(* Logix 5000 project; controller TEG17328 vendor 1 type 14 code 54 rev 16.23; software revision 16.04 *)

TASK MainTask (continuous, watchdog 500 ms) : MainProgram

MODULES
   Local : vendor 1 type 14 code 54 (ICP 2, rev 16.23)
      MNETC : vendor 1 type 0 code 15 (ICP 1, rev 1.1, Output RPI 5 ms)
END_MODULES

TYPE MNETCBLOCKSTATS :   // This object is used to store the block transfer statistics for the MVI56E-MNETC module.
STRUCT
   Read : INT;   // Total number of read block transfers
   Write : INT;   // Total number of write block transfers
   Parse : INT;   // Total number of blocks parsed
   Event : INT;   // Total number of event blocks received
   Cmd : INT;   // Total number of command blocks received
   Err : INT;   // Total number of block transfer errors
END_STRUCT
END_TYPE

TYPE MNETCCLIENTSTATS :   // This object is used to store the port statistics for an MVI56E-MNETC port.
STRUCT
   CmdReq : INT;   // Total number of command list requests sent
   CmdResp : INT;   // Total number of command list responses received
   CmdErr : INT;   // Total number of command list errors
   Requests : INT;   // Total number of requests for port
   Responses : INT;   // Total number of responses for port
   ErrSent : INT;   // Total number of errors sent
   ErrRec : INT;   // Total number of errors received
   CfgErrWord : INT;   // Configuration Error Word
   CurErr : INT;   // Current Error code
   LastErr : INT;   // Last recorded error code
END_STRUCT
END_TYPE

TYPE MNETCCLOCKTYPE :   // Allows read/write of clock value between the module and processor
STRUCT
   Read : BOOL;   // Reads current time from the module
   Write : BOOL;   // Writes current time from the module
   Config : MNETCDATETIME;   // Date and time configuration read or written between the module and processor
END_STRUCT
END_TYPE

TYPE MNETCCMDCLIENTSEQ_PENDING :   // Event sequence event cmd pending status
STRUCT
   Trigger : BOOL;   // Triggers event sequence cmd pending status
   Client0_QueueCount : SINT;   // Command queue count for client 0
   Client0_WaitingMsgs : SINT;   // Event sequence messages waiting for client 0
   Client1_QueueCount : SINT;   // Command queue count for client 1
   Client1_WaitingMsgs : SINT;   // Event sequence messages waiting for client 1
   Client2_QueueCount : SINT;   // Command queue count for client 2
   Client2_WaitingMsgs : SINT;   // Event sequence messages waiting for client 2
   Client3_QueueCount : SINT;   // Command queue count for client 3
   Client3_WaitingMsgs : SINT;   // Event sequence messages waiting for client 3
   Client4_QueueCount : SINT;   // Command queue count for client 4
   Client4_WaitingMsgs : SINT;   // Event sequence messages waiting for client 4
   Client5_QueueCount : SINT;   // Command queue count for client 5
   Client5_WaitingMsgs : SINT;   // Event sequence messages waiting for client 5
   Client6_QueueCount : SINT;   // Command queue count for client 6
   Client6_WaitingMsgs : SINT;   // Event sequence messages waiting for client 6
   Client7_QueueCount : SINT;   // Command queue count for client 7
   Client7_WaitingMsgs : SINT;   // Event sequence messages waiting for client 7
   Client8_QueueCount : SINT;   // Command queue count for client 8
   Client8_WaitingMsgs : SINT;   // Event sequence messages waiting for client 8
   Client9_QueueCount : SINT;   // Command queue count for client 9
   Client9_WaitingMsgs : SINT;   // Event sequence messages waiting for client 9
   Client10_QueueCount : SINT;   // Command queue count for client 10
   Client10_WaitingMsgs : SINT;   // Event sequence messages waiting for client 10
   Client11_QueueCount : SINT;   // Command queue count for client 11
   Client11_WaitingMsgs : SINT;   // Event sequence messages waiting for client 11
   Client12_QueueCount : SINT;   // Command queue count for client 12
   Client12_WaitingMsgs : SINT;   // Event sequence messages waiting for client 12
   Client13_QueueCount : SINT;   // Command queue count for client 13
   Client13_WaitingMsgs : SINT;   // Event sequence messages waiting for client 13
   Client14_QueueCount : SINT;   // Command queue count for client 14
   Client14_WaitingMsgs : SINT;   // Event sequence messages waiting for client 14
   Client15_QueueCount : SINT;   // Command queue count for client 15
   Client15_WaitingMsgs : SINT;   // Event sequence messages waiting for client 15
   Client16_QueueCount : SINT;   // Command queue count for client 16
   Client16_WaitingMsgs : SINT;   // Event sequence messages waiting for client 16
   Client17_QueueCount : SINT;   // Command queue count for client 17
   Client17_WaitingMsgs : SINT;   // Event sequence messages waiting for client 17
   Client18_QueueCount : SINT;   // Command queue count for client 18
   Client18_WaitingMsgs : SINT;   // Event sequence messages waiting for client 18
   Client19_QueueCount : SINT;   // Command queue count for client 19
   Client19_WaitingMsgs : SINT;   // Event sequence messages waiting for client 19
   Client20_QueueCount : SINT;   // Command queue count for client 20
   Client20_WaitingMsgs : SINT;   // Event sequence messages waiting for client 20
   Client21_QueueCount : SINT;   // Command count for client 21
   Client21_WaitingMsgs : SINT;   // Event sequence messages waiting for client 21
   Client22_QueueCount : SINT;   // Command queue count for client 22
   Client22_WaitingMsgs : SINT;   // Event sequence messages waiting for client 22
   Client23_QueueCount : SINT;   // Command queue count for client 23
   Client23_WaitingMsgs : SINT;   // Event sequence messages waiting for client 23
   Client24_QueueCount : SINT;   // Command queue count for client 24
   Client24_WaitingMsgs : SINT;   // Event sequence messages waiting for client 24
   Client25_QueueCount : SINT;   // Command queue count for client 25
   Client25_WaitingMsgs : SINT;   // Event sequence messages waiting for client 25
   Client26_QueueCount : SINT;   // Command queue count for client 26
   Client26_WaitingMsgs : SINT;   // Event sequence messages waiting for client 26
   Client27_QueueCount : SINT;   // Command queue count for client 27
   Client27_WaitingMsgs : SINT;   // Event sequence messages waiting for client 27
   Client28_QueueCount : SINT;   // Command queue count for client 28
   Client28_WaitingMsgs : SINT;   // Event sequence message waiting for client 28
   Client29_QueueCount : SINT;   // Command queue count for client 29
   Client29_WaitingMsgs : SINT;   // Event sequence messages waiting for client 29
END_STRUCT
END_TYPE

TYPE MNETCCMDCONTROL :   // MVI56E-MNETC Command Control
STRUCT
   ClientID : INT;   // Block5000 Client Identification by Index number 0 to 29
   CMDqty : INT;   // Block5000 command quantity
   CmdIndex : INT[16];   // Contains index in the command list for the 1st command to be entered into Command queue
   WriteCmdBits : INT[30];   // Command Bit control ClientID(0 to 29)
END_STRUCT
END_TYPE

TYPE MNETCCONTROL :   // Values used by program for data transfer operation between the module and the processor.
STRUCT
   BootTimer : TIMER;   // Timer used to clear both cold and warm boot requests
   ColdBoot : BOOL;   // Hardware reset of the Module
   WarmBoot : BOOL;   // Configuration data reset in the Module.
   ResetStatus : BOOL;   // Resets module status
   CmdID : INT;   // Command ID from 1 to 16
   CmdControl : MNETCCMDCONTROL;   // Holds Command Control statistics
   CmdControlPending : BOOL;   // Halts rung until Module is ready.
   CmdControlTrigger : BOOL;   // Command Control Trigger
   IPAddress : MNETCIPADDRESS;   // Getting and Setting IP address to and from Module
   EventCmd : MNETCEVENTCMD;   // Holds Event Command configuration
   EventSeqCmd : MNETCEVENTCMD_SEQ;   // Event Sequence Commands
END_STRUCT
END_TYPE

TYPE MNETCDATA :   // Contains Read Data (data read from the module to the processor) and Write Data (data written from the processor to the module)
STRUCT
   ReadData : INT[600];   // Data read from module. Set array equal to the size set in the Configuration file.
   WriteData : INT[600];   // Data to write to module. Set array equal to the size set in the Configuration file.
END_STRUCT
END_TYPE

TYPE MNETCDATETIME :   // Stores the date and time value
STRUCT
   Year : DINT;   // Displays module current year
   Month : DINT;   // Displays Module current month
   Day : DINT;   // Displays Module current day
   Hour : DINT;   // Displays Module current hour
   Minute : DINT;   // Displays Module current minute
   Seconds : DINT;   // Displays Module current second
END_STRUCT
END_TYPE

TYPE MNETCETHERNET :   // Stores the MVI56E-MNETC IP settings
STRUCT
   IP : INT[4];   // Module IP address
   Netmask : INT[4];   // Net mask used by the Module
   Gateway : INT[4];   // Gateway used by the module
END_STRUCT
END_TYPE

TYPE MNETCETHERNETTYPE :   // Allows read/write Ethernet settings between the module and processor
STRUCT
   Read : BOOL;   // Enable Ethernet configuration transfer from module to processor
   Write : BOOL;   // Enable Ethernet configuration transfer from processor to module
   Config : MNETCETHERNET;   // Module ethernet configurations ip, netmask and gateway
END_STRUCT
END_TYPE

TYPE MNETCEVENTCMD :   // Event command data structure
STRUCT
   Trigger : BOOL;   // Triggers event command
   ClientID : INT;   // Client ID for event command
   Cmd : MNETCEVENTCMD_SINGLE[30];   // Event command list
END_STRUCT
END_TYPE

TYPE MNETCEVENTCMD_SEQ :   // Data structure to use for each event command with status tracking by sequence number (blocks 4000 to 4029).
STRUCT
   Trigger : BOOL;   // Trigger Event Sequence Command
   ClientID : INT;   // Client ID for event sequence command (0-29)
   IP0 : INT;   // First digit of IP address
   IP1 : INT;   // Second digit of IP address
   IP2 : INT;   // Third digit of IP address
   IP3 : INT;   // Last digit of IP address
   ServPort : INT;   // TCP Service Port number (0-65535), 502 for MBAP, 2000 for MNET
   Node : INT;   // Modbus slave node address (0 to 247)
   DBAddress : INT;   // Module internal database to use with message
   Count : INT;   // Register or data point count
   Swap : INT;   // Swap code to use with functions 3 and 4
   Function : INT;   // Modbus function code for message
   Address : INT;   // Address to interface within device
   Sequence : INT;   // Unique sequence number to keep track of status code
END_STRUCT
END_TYPE

TYPE MNETCEVENTCMD_SEQSTAT :   // Event Command Sequence Status for one client
STRUCT
   Trigger : BOOL;   // Triggers event sequence command
   ClientID : INT;   // Selects ClientID
   Client : MNETCEVENTCMD_SEQSTAT_CLIENT[30];   // Error Status Event
END_STRUCT
END_TYPE

TYPE MNETCEVENTCMD_SEQSTAT_CLIENT :   // Event Command Sequence Status for one client
STRUCT
   Count : INT;   // Number of event commands received
   Cmd : MNETCEVENTCMD_SEQSTAT_SEQ_ERR[15];   // Error Status Event
END_STRUCT
END_TYPE

TYPE MNETCEVENTCMD_SEQSTAT_SEQ_ERR :   // Mnet event status of sequence event commands
STRUCT
   Sequence : INT;   // Sequence Number
   Error : INT;   // Error Code
END_STRUCT
END_TYPE

TYPE MNETCEVENTCMD_SINGLE :   // Data structure to use for Event message generation.
STRUCT
   IP0 : INT;   // First digit of IP address
   IP1 : INT;   // Second digit of IP address
   IP2 : INT;   // Third digit of IP address
   IP3 : INT;   // Last digit of IP address
   ServPort : INT;   // TCP Service Port number (0-65535), 502 for MBAP, 2000 for MNET
   Node : INT;   // Modbus slave node address (0 to 247)
   DBAddress : INT;   // Module internal database to use with message
   Count : INT;   // Register or data point count
   Swap : INT;   // Swap code to use with functions 3 and 4
   Function : INT;   // Modbus function code for message
   Address : INT;   // Address to interface with in device
END_STRUCT
END_TYPE

TYPE MNETCINITOUTDATA :   // Used to bring the Module into a known state after a restart operation.
STRUCT
   InitOutBlkIDLim : INT;   // Block Index Limit for ReadData size of the array
END_STRUCT
END_TYPE

TYPE MNETCIPADDRESS :   // Data structure to get and set the IP address of the module.
STRUCT
   IPGetTrigger : BOOL;   // Gets IP address.
   IPReceived : INT[4];   // IP address received.
   IPSetTrigger : BOOL;   // Sets IP address
   IPRequested : INT[4];   // IP address set.
END_STRUCT
END_TYPE

TYPE MNETCMODULEDEF :   // This defines the whole module which includes all tags used in the program
STRUCT
   DATA : MNETCDATA;   // Data read from module
   CONTROL : MNETCCONTROL;   // Client ,Server Status and blocks status
   STATUS : MNETCSTATUS;   // MNETC Module control
   UTIL : MNETCUTIL;   // Block statistics
END_STRUCT
END_TYPE

TYPE MNETCPASSTHRU :
STRUCT
   MBControl1 : CONTROL;   // Modbus pass thru message control
   MBControl2 : CONTROL;   // Modbus pass thru message control
   Mbdouble : DINT;   // Modbus double int tag
   MBMsg : SINT[500];   // Message array
   MBMsgLen : INT;   // Message length
   MBOffset : INT;   // Start offset in the message
   MBOffsetBit : INT;   // Offset bit in the message
   MBScratch : INT[3];   // Temporary used ints
   MBboolLength : DINT;   // Holds Word size that will accommodate Coil Qty.
   MBSpecial : INT[4];   // Holds Special Function 99 data.
   And_Mask : INT;   // Function 22 "AND" Mask
   Or_Mask : INT;   // Function 22 "OR" Mask
END_STRUCT
END_TYPE

TYPE MNETCSERVERS :   // This object is used to store the Server statistics for an MVI56E-MNETC port.
STRUCT
   MNET : MNETCSERVERSTATS;   // Server status for TCP port 2000
   MBAP : MNETCSERVERSTATS;   // Server status for TCP port 502
END_STRUCT
END_TYPE

TYPE MNETCSERVERSTATS :
STRUCT
   Requests : INT;   // Total number of request sent
   Responses : INT;   // Total number of responses received
   ErrSent : INT;   // Total number of errors sent
   ErrRec : INT;   // Total number of errors received
END_STRUCT
END_TYPE

TYPE MNETCSTATUS :   // This status data is returned on each read block and can be used to detect proper module operation.
STRUCT
   PassCnt : INT;   // Program cycle counter
   ProductVersion : INT;   // This is used to pass the product version to the processor
   ProductCode : INT[2];   // This is used to pass the product Code to the processor
   BlockStats : MNETCBLOCKSTATS;   // Block transfer statistics
   CmdBits : INT[30];   // Commands bits array to be used for 30 clients
   ClientStatsTrigger : BOOL;   // Get Client Status
   ClientID : INT;   // Client ID to get Status From
   ClientStatus : MNETCCLIENTSTATS[30];   // Client status data
   CmdErrorList : INT[16];   // Command Error List
   EventSeqCmdPending : MNETCCMDCLIENTSEQ_PENDING;   // Stores information on the number of seq events pending in the module
   EventSeqCmd : MNETCEVENTCMD_SEQSTAT;   // Event seq event commands pending
   EventSeqReady : DINT;   // Bit mapped for Status data (bit=1 data ready, bit = 0 no event data)
   ServerStatsTrigger : BOOL;   // Get Server Status
   ServerStatus : MNETCSERVERS;   // Server status data
END_STRUCT
END_TYPE

TYPE MNETCUTIL :   // Values used by program for data transfer operation between the module and the processor.
STRUCT
   LastRead : INT;   // Index of last read block
   LastWrite : INT;   // Index of last write block
   BlockIndex : INT;   // Computed block offset for data table
   StatusIndex : INT;   // Computed block offset for status data
   ReadDataSizeGet : INT;   // Gets ReadData Array Length.
   WriteDataSizeGet : INT;   // Gets WriteData Array Length.
   ReadDataBlkCount : INT;   // Holds the value of the Block Counts of the Read Data Array.
   WriteDataBlkCount : INT;   // Holds the value of the Block Counts of the Write Data Array.
   RBTSremainder : INT;   // Holds remainder calculation value from the read array.
   WBTSremainder : INT;   // Holds remainder calculation value from the write array.
   PassThru : MNETCPASSTHRU;
   IPsetPending : BOOL;   // Allows Setting module IP address
   IPgetPending : BOOL;   // Allows Getting module IP address
   InitOutputData : MNETCINITOUTDATA;
   FaultCode : INT;   // Fault Code value
   CheckInitialization : BOOL;   // Check Initialization trigger
   StatusSeqIndex : INT;   // Computed block offset for status data
END_STRUCT
END_TYPE

ADD_ON_INSTRUCTION AOI56EMNETC_Optional   (* revision 1.0 *)
// MVI56E-MNETC Optional Add-On Ethernet/Clock
// Revision note:
// v1.0 - Release.
VAR_IN_OUT
   MVI56MNETCEthernet : MNETCETHERNETTYPE; {required}   // MVI56E-MNET Rev2 Ethernet Settings
   MVI56MNETCClock : MNETCCLOCKTYPE; {required}   // MVI56E-MNET Rev2 Clock Settings
   ReadEthernetMSG : MESSAGE; {required}   // Read Ethernet Settings Message
   WriteEthernetMSG : MESSAGE; {required}   // Write Ethernet Settings Message
   ReadClockMSG : MESSAGE; {required}   // Read Clock Settings Message
   WriteClockMSG : MESSAGE; {required}   // Write Clock Settings Message
END_VAR

ROUTINE Logic   (* ladder *)
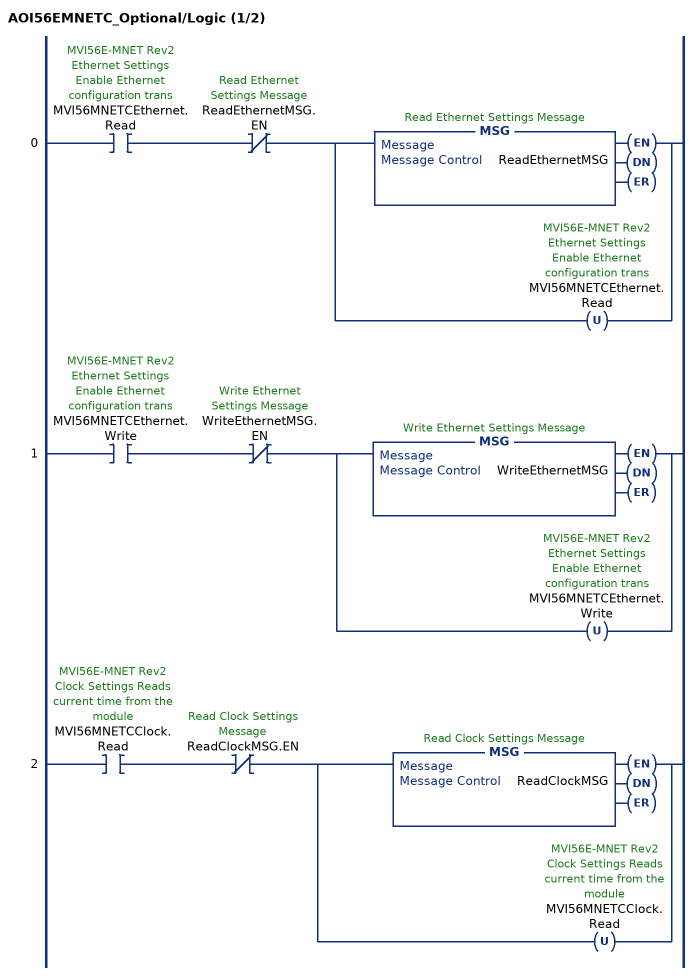
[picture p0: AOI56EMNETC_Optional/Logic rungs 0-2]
   0: XIC(MVI56MNETCEthernet.Read)XIO(ReadEthernetMSG.EN)[MSG(ReadEthernetMSG) ,OTU(MVI56MNETCEthernet.Read) ];
   1: XIC(MVI56MNETCEthernet.Write)XIO(WriteEthernetMSG.EN)[MSG(WriteEthernetMSG) ,OTU(MVI56MNETCEthernet.Write) ];
   2: XIC(MVI56MNETCClock.Read)XIO(ReadClockMSG.EN)[MSG(ReadClockMSG) ,OTU(MVI56MNETCClock.Read) ];
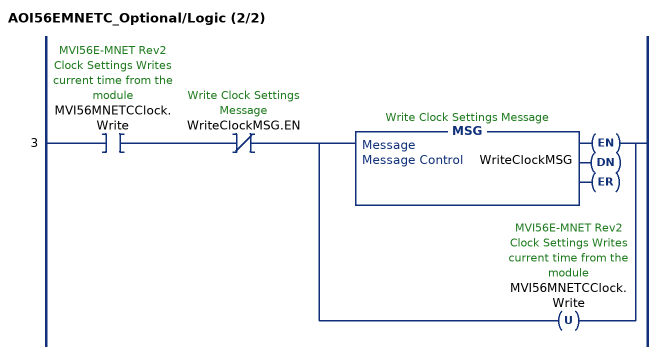
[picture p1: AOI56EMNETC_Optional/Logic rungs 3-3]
   3: XIC(MVI56MNETCClock.Write)XIO(WriteClockMSG.EN)[MSG(WriteClockMSG) ,OTU(MVI56MNETCClock.Write) ];
END_ROUTINE
END_ADD_ON_INSTRUCTION

ADD_ON_INSTRUCTION AOI56MNETC   (* revision 1.10, ExecutePrescan *)
// Add-On for  MVI56E-MNETC modules with firmware version 3.01 and newer.
// Revision note:
// v1.10 -  Enables all commands as a default by setting all WriteCmdBits to 1.
VAR_IN_OUT
   Connection_Input : INT[250]; {required}   // Input parameters.
   Connection_Output : INT[248]; {required}   // Output parameters.
   MNETC : MNETCMODULEDEF; {required}
END_VAR
VAR
   MJFAULTS : DINT[12];
END_VAR

ROUTINE Logic   (* ladder *)
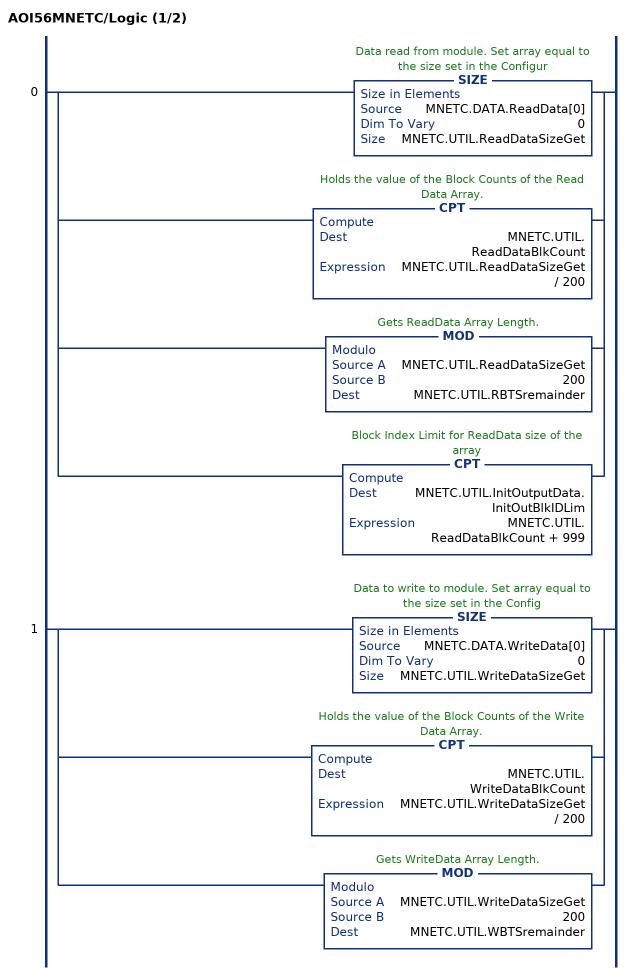
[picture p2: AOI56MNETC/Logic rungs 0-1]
   0: [SIZE(MNETC.DATA.ReadData[0],0,MNETC.UTIL.ReadDataSizeGet) ,CPT(MNETC.UTIL.ReadDataBlkCount,MNETC.UTIL.ReadDataSizeGet / 200) ,MOD(MNETC.UTIL.ReadDataSizeGet,200,MNETC.UTIL.RBTSremainder) ,CPT(MNETC.UTIL.InitOutputData.InitOutBlkIDLim,MNETC.UTIL.ReadDataBlkCount + 999) ];
   1: [SIZE(MNETC.DATA.WriteData[0],0,MNETC.UTIL.WriteDataSizeGet) ,CPT(MNETC.UTIL.WriteDataBlkCount,MNETC.UTIL.WriteDataSizeGet / 200) ,MOD(MNETC.UTIL.WriteDataSizeGet,200,MNETC.UTIL.WBTSremainder) ];
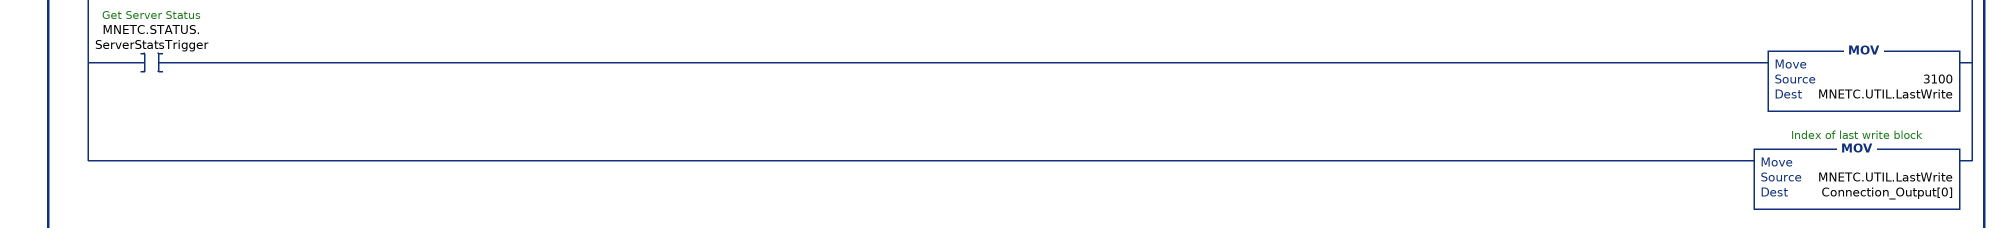
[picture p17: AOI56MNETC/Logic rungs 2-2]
   2: NEQ(Connection_Input[249],MNETC.UTIL.LastRead)[MOV(Connection_Input[249],MNETC.UTIL.LastRead) ,GRT(MNETC.UTIL.FaultCode,0) OTL(MNETC.UTIL.CheckInitialization) ,EQU(MNETC.UTIL.FaultCode,0) NEQ(MNETC.UTIL.LastRead,0) OTU(MNETC.UTIL.CheckInitialization) ,EQU(MNETC.UTIL.FaultCode,0) [EQU(-1,MNETC.UTIL.LastRead) ,EQU(0,MNETC.UTIL.LastRead) ] XIO(MNETC.UTIL.CheckInitialization) [[EQU(MNETC.STATUS.ProductCode[1],13637) GEQ(MNETC.STATUS.ProductVersion,204) ,EQU(MNETC.STATUS.ProductCode[1],13635) GEQ(MNETC.STATUS.ProductVersion,113) ] [GEQ(MNETC.UTIL.ReadDataSizeGet,200) COP(Connection_Input[2],MNETC.DATA.ReadData[0],200) ,LES(MNETC.UTIL.ReadDataSizeGet,200) COP(Connection_Input[2],MNETC.DATA.ReadData[0],MNETC.UTIL.RBTSremainder) ] ,COP(Connection_Input[202],MNETC.STATUS.PassCnt,1) ,COP(Connection_Input[203],MNETC.STATUS.BlockStats.Read,6) ,COP(Connection_Input[209],MNETC.STATUS.CmdBits[0],30) ,COP(Connection_Input[239],MNETC.STATUS.ProductCode[0],2) ,COP(Connection_Input[241],MNETC.STATUS.ProductVersion,1) ,COP(Connection_Input[242],MNETC.STATUS.EventSeqReady,1) ] ,GEQ(MNETC.UTIL.LastRead,1) [LEQ(MNETC.UTIL.LastRead,MNETC.UTIL.ReadDataBlkCount) [CPT(MNETC.UTIL.BlockIndex,(MNETC.UTIL.LastRead-1)*200) ,COP(Connection_Input[2],MNETC.DATA.ReadData[MNETC.UTIL.BlockIndex],200) ,COP(Connection_Input[202],MNETC.STATUS.PassCnt,1) ,COP(Connection_Input[203],MNETC.STATUS.BlockStats.Read,6) ,COP(Connection_Input[209],MNETC.STATUS.CmdBits[0],30) ,COP(Connection_Input[239],MNETC.STATUS.ProductCode[0],2) ,COP(Connection_Input[241],MNETC.STATUS.ProductVersion,1) ,COP(Connection_Input[242],MNETC.STATUS.EventSeqReady,1) ] ,CMP(MNETC.UTIL.LastRead - MNETC.UTIL.ReadDataBlkCount = 1) GRT(MNETC.UTIL.RBTSremainder,0) [CPT(MNETC.UTIL.BlockIndex,(MNETC.UTIL.LastRead - 1) * 200) ,COP(Connection_Input[2],MNETC.DATA.ReadData[MNETC.UTIL.BlockIndex],MNETC.UTIL.RBTSremainder) ,COP(Connection_Input[202],MNETC.STATUS.PassCnt,1) ,COP(Connection_Input[203],MNETC.STATUS.BlockStats.Read,6) ,COP(Connection_Input[209],MNETC.STATUS.CmdBits[0],30) ,COP(Connection_Input[239],MNETC.STATUS.ProductCode[0],2) ,COP(Connection_Input[241],MNETC.STATUS.ProductVersion,1) ,COP(Connection_Input[242],MNETC.STATUS.EventSeqReady,1) ] ] ,LIM(9956,MNETC.UTIL.LastRead,9996) [EQU(9996,MNETC.UTIL.LastRead) [MOV(Connection_Input[2],MNETC.UTIL.PassThru.MBMsgLen) ,COP(Connection_Input[4],MNETC.UTIL.PassThru.MBMsg[0],MNETC.UTIL.PassThru.MBMsgLen) ] ,LIM(9956,MNETC.UTIL.LastRead,9957) [MOV(Connection_Input[3],MNETC.UTIL.PassThru.MBOffset) ,LES(MNETC.UTIL.PassThru.MBOffset,MNETC.UTIL.WriteDataSizeGet) COP(Connection_Input[4],MNETC.DATA.WriteData[MNETC.UTIL.PassThru.MBOffset],Connection_Input[2]) ] ,EQU(9958,MNETC.UTIL.LastRead) [MOV(Connection_Input[3],MNETC.UTIL.PassThru.MBOffsetBit) ,MOV(Connection_Input[4],MNETC.UTIL.PassThru.MBScratch[2]) ,DIV(MNETC.UTIL.PassThru.MBOffsetBit,16,MNETC.UTIL.PassThru.MBOffset) ,MOD(MNETC.UTIL.PassThru.MBOffsetBit,16,MNETC.UTIL.PassThru.MBOffsetBit) ,XPY(2,MNETC.UTIL.PassThru.MBOffsetBit,MNETC.UTIL.PassThru.mbdouble) ,MVM(MNETC.UTIL.PassThru.mbdouble,16#0000_ffff,MNETC.UTIL.PassThru.MBOffsetBit) ,GEQ(MNETC.UTIL.PassThru.MBOffset,0) LES(MNETC.UTIL.PassThru.MBOffset,MNETC.UTIL.WriteDataSizeGet) LEQ(MNETC.UTIL.PassThru.MBOffset,2048) [NEQ(MNETC.UTIL.PassThru.MBScratch[2],0) OR(MNETC.UTIL.PassThru.MBOffsetBit,MNETC.DATA.WriteData[MNETC.UTIL.PassThru.MBOffset],MNETC.DATA.WriteData[MNETC.UTIL.PassThru.MBOffset]) ,EQU(MNETC.UTIL.PassThru.MBScratch[2],0) [NOT(MNETC.UTIL.PassThru.MBOffsetBit,MNETC.UTIL.PassThru.MBOffsetBit) ,AND(MNETC.UTIL.PassThru.MBOffsetBit,MNETC.DATA.WriteData[MNETC.UTIL.PassThru.MBOffset],MNETC.DATA.WriteData[MNETC.UTIL.PassThru.MBOffset]) ] ] ] ,EQU(9959,MNETC.UTIL.LastRead) [[MOV(Connection_Input[3],MNETC.UTIL.PassThru.MBOffset) ,MOV(Connection_Input[2],MNETC.UTIL.PassThru.MBControl1.LEN) ,MOV(Connection_Input[2],MNETC.UTIL.PassThru.MBControl2.LEN) ,CPT(MNETC.UTIL.PassThru.MBboolLength,MNETC.UTIL.PassThru.MBOffset+MNETC.UTIL.PassThru.MBControl1.LEN) ] ,LEQ(MNETC.UTIL.PassThru.MBboolLength,MNETC.UTIL.WriteDataSizeGet) [FAL(MNETC.UTIL.PassThru.MBControl1,?,?,ALL,MNETC.DATA.WriteData[MNETC.UTIL.PassThru.MBOffset+MNETC.UTIL.PassThru.MBControl1.POS],MNETC.DATA.WriteData[MNETC.UTIL.PassThru.MBOffset+MNETC.UTIL.PassThru.MBControl1.POS] AND(NOT Connection_Input[54+MNETC.UTIL.PassThru.MBControl1.POS])) ,FAL(MNETC.UTIL.PassThru.MBControl2,?,?,ALL,MNETC.DATA.WriteData[MNETC.UTIL.PassThru.MBOffset+MNETC.UTIL.PassThru.MBControl2.POS],MNETC.DATA.WriteData[MNETC.UTIL.PassThru.MBOffset+MNETC.UTIL.PassThru.MBControl2.POS] OR(Connection_Input[54+MNETC.UTIL.PassThru.MBControl2.POS] AND Connection_Input[4+MNETC.UTIL.PassThru.MBControl2.POS])) ,RES(MNETC.UTIL.PassThru.MBControl1) ,RES(MNETC.UTIL.PassThru.MBControl2) ] ] ,EQU(MNETC.UTIL.LastRead,9960) LIM(0,Connection_Input[3],MNETC.UTIL.WriteDataSizeGet) [MOV(Connection_Input[3],MNETC.UTIL.PassThru.MBOffset) ,MOV(Connection_Input[4],MNETC.UTIL.PassThru.And_Mask) ,MOV(Connection_Input[5],MNETC.UTIL.PassThru.Or_Mask) ,CPT(MNETC.DATA.WriteData[MNETC.UTIL.PassThru.MBOffset],(MNETC.DATA.WriteData[MNETC.UTIL.PassThru.MBOffset] AND MNETC.UTIL.PassThru.And_Mask)OR(MNETC.UTIL.PassThru.Or_Mask AND (NOT(MNETC.UTIL.PassThru.And_Mask)))) ] ,EQU(MNETC.UTIL.LastRead,9961) LIM(0,Connection_Input[3],MNETC.UTIL.WriteDataSizeGet) [MOV(Connection_Input[3],MNETC.UTIL.PassThru.MBOffset) ,MOV(Connection_Input[2],MNETC.UTIL.PassThru.MBMsgLen) ,COP(Connection_Input[4],MNETC.DATA.WriteData[MNETC.UTIL.PassThru.MBOffset],MNETC.UTIL.PassThru.MBMsgLen) ] ,EQU(9970,MNETC.UTIL.LastRead) COP(Connection_Output[0],MNETC.UTIL.PassThru.MBSpecial[0],4) ] ,LIM(3000,MNETC.UTIL.LastRead,3029) [CPT(MNETC.UTIL.StatusIndex,MNETC.UTIL.LastRead-3000) ,COP(Connection_Input[3],MNETC.STATUS.ClientStatus[MNETC.UTIL.StatusIndex].CmdReq,10) ,COP(Connection_Input[13],MNETC.STATUS.CmdErrorList[0],16) ,OTU(MNETC.STATUS.ClientStatsTrigger) ] ,EQU(3100,MNETC.UTIL.LastRead) [[COP(Connection_Input[6],MNETC.STATUS.ServerStatus.MNET.Requests,4) ,COP(Connection_Input[16],MNETC.STATUS.ServerStatus.MBAP.Requests,4) ] ,OTU(MNETC.STATUS.ServerStatsTrigger) ] ,EQU(MNETC.UTIL.LastRead,9990) [COP(Connection_Input[2],MNETC.CONTROL.IPAddress.IPRequested[0],4) ,OTU(MNETC.UTIL.IPsetPending) ] ,EQU(MNETC.UTIL.LastRead,9991) [COP(Connection_Input[2],MNETC.CONTROL.IPAddress.IPReceived[0],4) ,OTU(MNETC.UTIL.IPgetPending) ] ,XIC(MNETC.CONTROL.CmdControlTrigger) LIM(5001,MNETC.UTIL.LastRead,5016) LIM(1,Connection_Input[2],16) OTU(MNETC.CONTROL.CmdControlTrigger) ,XIC(MNETC.CONTROL.EventCmd.Trigger) LIM(2000,MNETC.UTIL.LastRead,2029) EQU(Connection_Input[2],1) OTU(MNETC.CONTROL.EventCmd.Trigger) ,XIC(MNETC.CONTROL.EventSeqCmd.Trigger) LIM(4000,MNETC.UTIL.LastRead,4029) EQU(Connection_Input[2],1) OTU(MNETC.CONTROL.EventSeqCmd.Trigger) ,LIM(4100,MNETC.UTIL.LastRead,4129) [CPT(MNETC.UTIL.StatusSeqIndex,MNETC.UTIL.LastRead-4100) ,COP(Connection_Input[2],MNETC.STATUS.EventSeqCmd.Client[MNETC.UTIL.StatusSeqIndex].Count,1) ,COP(Connection_Input[3],MNETC.STATUS.EventSeqCmd.Client[MNETC.UTIL.StatusSeqIndex].Cmd[0],30) ,OTU(MNETC.STATUS.EventSeqCmd.Trigger) ] ,EQU(MNETC.UTIL.LastRead,4200) COP(Connection_Input[2],MNETC.STATUS.EventSeqCmdPending.Client0_QueueCount,60) ,MOV(Connection_Input[1],MNETC.UTIL.LastWrite) ,XIC(MNETC.CONTROL.WarmBoot) [MOV(9998,MNETC.UTIL.LastWrite) ,OTU(MNETC.CONTROL.WarmBoot) ] ,XIC(MNETC.CONTROL.ColdBoot) [MOV(9999,MNETC.UTIL.LastWrite) ,OTU(MNETC.CONTROL.ColdBoot) ] ,XIC(MNETC.CONTROL.ResetStatus) [MOV(9997,MNETC.UTIL.LastWrite) ,OTU(MNETC.CONTROL.ResetStatus) ] ,XIC(MNETC.CONTROL.IPAddress.IPSetTrigger) XIO(MNETC.UTIL.IPsetPending) [COP(MNETC.CONTROL.IPAddress.IPRequested[0],Connection_Output[1],4) ,MOV(9990,MNETC.UTIL.LastWrite) ,OTU(MNETC.CONTROL.IPAddress.IPSetTrigger) ,OTL(MNETC.UTIL.IPsetPending) ] ,XIC(MNETC.CONTROL.IPAddress.IPGetTrigger) XIO(MNETC.UTIL.IPgetPending) [MOV(9991,MNETC.UTIL.LastWrite) ,OTU(MNETC.CONTROL.IPAddress.IPGetTrigger) ,OTL(MNETC.UTIL.IPgetPending) ] ,XIC(MNETC.CONTROL.CmdControlTrigger) LIM(1,MNETC.CONTROL.CmdID,16) [LIM(0,MNETC.CONTROL.CmdControl.ClientID,29) MOV(MNETC.CONTROL.CmdControl.ClientID,Connection_Output[1]) ,COP(MNETC.CONTROL.CmdControl.CmdIndex[0],Connection_Output[2],16) ,ADD(5000,MNETC.CONTROL.CmdID,MNETC.UTIL.LastWrite) ] ,XIC(MNETC.CONTROL.EventSeqCmd.Trigger) LIM(0,MNETC.CONTROL.EventSeqCmd.ClientID,29) [ADD(4000,MNETC.CONTROL.EventSeqCmd.ClientID,MNETC.UTIL.LastWrite) ,COP(MNETC.CONTROL.EventSeqCmd.IP0,Connection_Output[1],12) ] ,XIC(MNETC.CONTROL.EventCmd.Trigger) LIM(0,MNETC.CONTROL.EventCmd.ClientID,29) [ADD(2000,MNETC.CONTROL.EventCmd.ClientID,MNETC.UTIL.LastWrite) ,COP(MNETC.CONTROL.EventCmd.Cmd[MNETC.CONTROL.EventCmd.ClientID].IP0,Connection_Output[1],11) ] ,XIC(MNETC.STATUS.EventSeqCmdPending.Trigger) [MOV(4200,MNETC.UTIL.LastWrite) ,OTU(MNETC.STATUS.EventSeqCmdPending.Trigger) ] ,GEQ(MNETC.UTIL.LastWrite,1) [LEQ(MNETC.UTIL.LastWrite,MNETC.UTIL.WriteDataBlkCount) [CPT(MNETC.UTIL.BlockIndex,(MNETC.UTIL.LastWrite-1)*200) ,COP(MNETC.DATA.WriteData[MNETC.UTIL.BlockIndex],Connection_Output[1],200) ,COP(MNETC.CONTROL.CmdControl.WriteCmdBits[0],Connection_Output[201],30) ] ,CMP(MNETC.UTIL.LastWrite - MNETC.UTIL.WriteDataBlkCount = 1) GRT(MNETC.UTIL.WBTSremainder,0) [CPT(MNETC.UTIL.BlockIndex,(MNETC.UTIL.LastWrite - 1) * 200) ,COP(MNETC.DATA.WriteData[MNETC.UTIL.BlockIndex],Connection_Output[1],MNETC.UTIL.WBTSremainder) ,COP(MNETC.CONTROL.CmdControl.WriteCmdBits[0],Connection_Output[201],30) ] ] ,LIM(1000,MNETC.UTIL.LastWrite,1049) LEQ(MNETC.UTIL.LastWrite,MNETC.UTIL.InitOutputData.InitOutBlkIDLim) [CPT(MNETC.UTIL.BlockIndex,(MNETC.UTIL.LastWrite-1000)*200) ,COP(MNETC.DATA.ReadData[MNETC.UTIL.BlockIndex],Connection_Output[1],200) ] ,[EQU(-1,MNETC.UTIL.LastWrite) ,EQU(0,MNETC.UTIL.LastWrite) ] [[EQU(MNETC.STATUS.ProductCode[1],13637) GEQ(MNETC.STATUS.ProductVersion,204) ,EQU(MNETC.STATUS.ProductCode[1],13635) GEQ(MNETC.STATUS.ProductVersion,113) ] [GEQ(MNETC.UTIL.WriteDataSizeGet,200) COP(MNETC.DATA.WriteData[0],Connection_Output[1],200) ,LES(MNETC.UTIL.WriteDataSizeGet,200) COP(MNETC.DATA.WriteData[0],Connection_Output[1],MNETC.UTIL.WBTSremainder) ] ,COP(MNETC.CONTROL.CmdControl.WriteCmdBits[0],Connection_Output[201],30) ] ,XIC(MNETC.STATUS.EventSeqCmd.Trigger) LIM(0,MNETC.STATUS.EventSeqCmd.ClientID,29) ADD(4100,MNETC.STATUS.EventSeqCmd.ClientID,MNETC.UTIL.LastWrite) ,XIC(MNETC.STATUS.ClientStatsTrigger) LIM(0,MNETC.STATUS.ClientID,29) ADD(3000,MNETC.STATUS.ClientID,MNETC.UTIL.LastWrite) ,XIC(MNETC.STATUS.ServerStatsTrigger) MOV(3100,MNETC.UTIL.LastWrite) ,MOV(MNETC.UTIL.LastWrite,Connection_Output[0]) ];
END_ROUTINE

ROUTINE Prescan   (* ladder *)
// Prescan
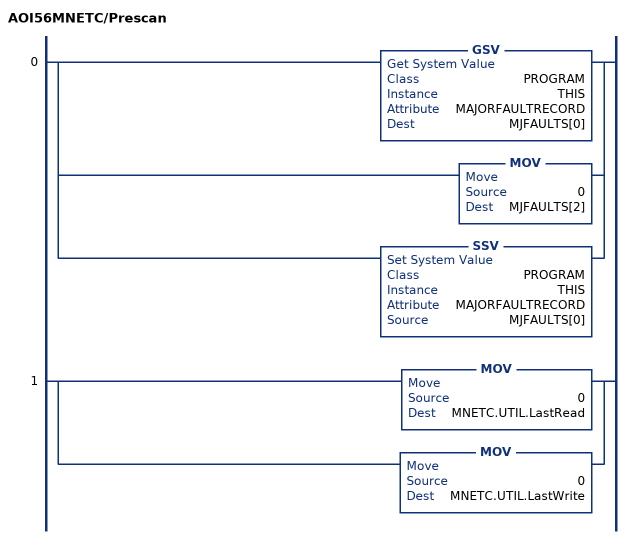
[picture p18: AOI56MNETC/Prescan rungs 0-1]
   0: [GSV(PROGRAM,THIS,MAJORFAULTRECORD,MJFAULTS[0]) ,MOV(0,MJFAULTS[2]) ,SSV(PROGRAM,THIS,MAJORFAULTRECORD,MJFAULTS[0]) ];
   1: [MOV(0,MNETC.UTIL.LastRead) ,MOV(0,MNETC.UTIL.LastWrite) ];
END_ROUTINE
END_ADD_ON_INSTRUCTION

VAR_GLOBAL   (* controller tags *)
   AOI56EMNETC_OPTIONAL : AOI56EMNETC_Optional;
   AOI56MNETC : AOI56MNETC;
   MNETC : MNETCMODULEDEF;
   MVI56EMNETCCLOCK : MNETCCLOCKTYPE;
   MVI56EMNETCETHERNET : MNETCETHERNETTYPE;
   READCLOCKMSG : MESSAGE;
        MessageParameters(ServiceCode := 16#000e, DestinationTag := MVI56EMNETCCLOCK.Config, ...)
   READETHERNETMSG : MESSAGE;
        MessageParameters(ServiceCode := 16#000e, DestinationTag := MVI56EMNETCETHERNET.Config, ...)
   WRITECLOCKMSG : MESSAGE;
        MessageParameters(ServiceCode := 16#0010, LocalElement := MVI56EMNETCCLOCK.Config, ...)
   WRITEETHERNETMSG : MESSAGE;
        MessageParameters(ServiceCode := 16#0010, LocalElement := MVI56EMNETCETHERNET.Config, ...)
END_VAR

PROGRAM MainProgram   (* main routine MainRoutine *)

ROUTINE MainRoutine   (* ladder *)
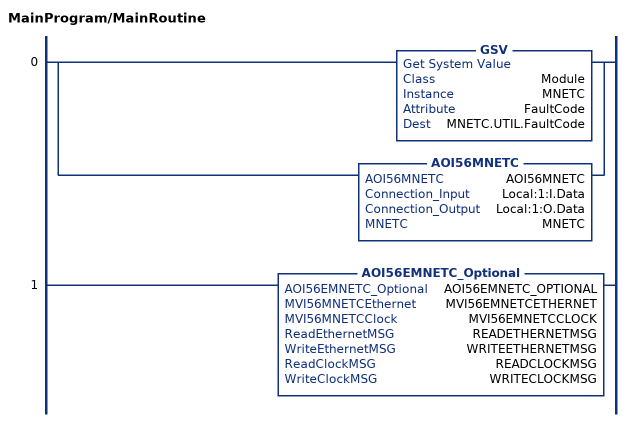
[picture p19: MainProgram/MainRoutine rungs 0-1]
   0: [GSV(Module,MNETC,FaultCode,MNETC.UTIL.FaultCode) ,AOI56MNETC(AOI56MNETC,Local:1:I.Data,Local:1:O.Data,MNETC) ];
   1: AOI56EMNETC_Optional(AOI56EMNETC_OPTIONAL,MVI56EMNETCETHERNET,MVI56EMNETCCLOCK,READETHERNETMSG,WRITEETHERNETMSG,READCLOCKMSG,WRITECLOCKMSG);
END_ROUTINE
END_PROGRAM
